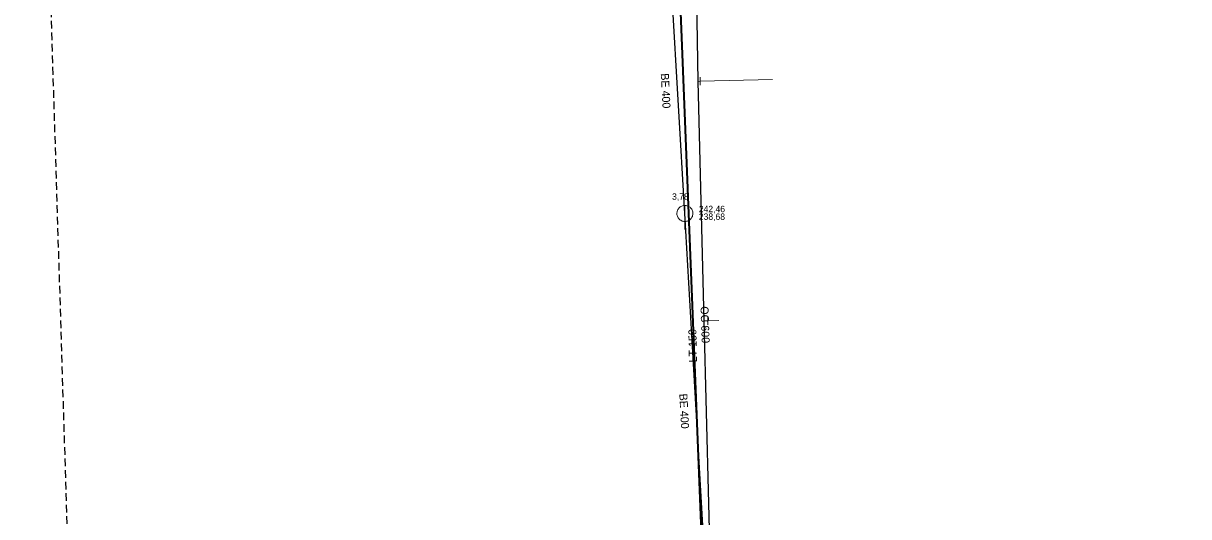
# Model space of a CAD drawing. Extents: x -777996 to -777727, y -976581 to -976199.
# Drawn here: x -777995.4 to -777849.8, y -976378.6 to -976316.9 of the extents above; entities that cross this region are included whole.
import ezdxf

# ---------------------------------------------------------------- set-up
doc = ezdxf.new("R2010")
doc.units = 0
doc.header["$LTSCALE"] = 0.32
doc.linetypes.add('MEDIUM_DASHED', pattern=[4.5, 3, -1.5])
for name, color, linetype, lineweight in [('1', 7, 'MEDIUM_DASHED', 25), ('13', 7, 'Continuous', 13), ('14', 7, 'Continuous', 25), ('17', 7, 'Continuous', 25), ('22', 7, 'Continuous', 13), ('34', 7, 'Continuous', 13)]:
    doc.layers.add(name, color=color, linetype=linetype, lineweight=lineweight)

msp = doc.modelspace()

# ---------------------------------------------------------------- linework, layer by layer
at = {"layer": '1'}
msp.add_lwpolyline([(-777995.417, -976203.033), (-777848.18, -976198.846), (-777864.927, -976230.247), (-777726.762, -976491.225), (-777789.565, -976581.242), (-777941.686, -976558.215), (-777989.136, -976405.396)], close=True, dxfattribs=at)
at = {"layer": '13'}
for p, q in [((-777910.871, -976324.184), (-777901.835, -976323.954)), ((-777909.92, -976354.12), (-777908.556, -976354.054))]:
    msp.add_line(p, q, dxfattribs=at)
at = {"layer": '14'}
for p, q in [((-777912.781, -976340.699), (-777914.489, -976311.478)), ((-777909.866, -976391.528), (-777912.781, -976340.699))]:
    msp.add_line(p, q, dxfattribs=at)
at = {"layer": '14', "lineweight": 13}
for p, q in [((-777911.171, -976324.191), (-777910.871, -976324.184)), ((-777910.419, -976354.124), (-777909.92, -976354.12))]:
    msp.add_line(p, q, dxfattribs=at)
at = {"layer": '17', "lineweight": 35}
msp.add_lwpolyline([(-777904.212, -976563.887), (-777912, -976559.699), (-777928.6, -976551.899), (-777943.399, -976543.899), (-777945.899, -976539.199), (-777934, -976487.1), (-777919.8, -976463.1), (-777903.899, -976437), (-777908, -976421.399), (-777910, -976398.3), (-777913.399, -976312.399), (-777914.899, -976265.1)], dxfattribs=at)
at = {"layer": '17'}
msp.add_lwpolyline([(-777913.344, -976268.857), (-777912.789, -976277.989), (-777911.427, -976308.781), (-777911.171, -976324.191), (-777910.419, -976354.125), (-777909.559, -976388.363), (-777908.825, -976391.646), (-777908.211, -976394.397)], dxfattribs=at)
at = {"layer": '22'}
msp.add_line((-777912.781, -976342.699), (-777912.78, -976339.699), dxfattribs=at)
msp.add_lwpolyline([(-777911.781, -976340.699), (-777911.786, -976340.59), (-777911.804, -976340.482), (-777911.834, -976340.376), (-777911.874, -976340.275), (-777911.926, -976340.178), (-777911.988, -976340.088), (-777912.06, -976340.005), (-777912.14, -976339.931), (-777912.228, -976339.865), (-777912.322, -976339.81), (-777912.422, -976339.765), (-777912.527, -976339.732), (-777912.634, -976339.71), (-777912.743, -976339.7), (-777912.853, -976339.702), (-777912.961, -976339.716), (-777913.068, -976339.741), (-777913.171, -976339.778), (-777913.269, -976339.827), (-777913.361, -976339.885), (-777913.447, -976339.954), (-777913.524, -976340.031), (-777913.593, -976340.117), (-777913.652, -976340.209), (-777913.7, -976340.307), (-777913.737, -976340.41), (-777913.763, -976340.517), (-777913.777, -976340.625), (-777913.78, -976340.735), (-777913.77, -976340.844), (-777913.749, -976340.951), (-777913.715, -976341.055), (-777913.671, -976341.155), (-777913.616, -976341.25), (-777913.55, -976341.338), (-777913.476, -976341.418), (-777913.393, -976341.49), (-777913.303, -976341.552), (-777913.207, -976341.604), (-777913.105, -976341.645), (-777913, -976341.675), (-777912.892, -976341.693), (-777912.782, -976341.699), (-777912.673, -976341.693), (-777912.565, -976341.675), (-777912.46, -976341.646), (-777912.358, -976341.605), (-777912.261, -976341.553), (-777912.171, -976341.491), (-777912.088, -976341.42), (-777912.013, -976341.34), (-777911.948, -976341.252), (-777911.892, -976341.158), (-777911.848, -976341.058), (-777911.814, -976340.954), (-777911.792, -976340.846), (-777911.782, -976340.737)], close=True, dxfattribs=at)
at = {"layer": '34'}
for p, q in [((-777910.883, -976323.684), (-777910.859, -976324.683)), ((-777909.925, -976353.62), (-777909.915, -976354.619))]:
    msp.add_line(p, q, dxfattribs=at)

# ---------------------------------------------------------------- texts
at = {"layer": '1'}
for s, rotation, p in [('BE 400', 273, (-777915.792, -976323.209)), ('OC 600', 272, (-777910.833, -976352.313)), ('LT 150', 91, (-777911.274, -976359.3)), ('BE 400', 273, (-777913.476, -976363.231))]:
    msp.add_text(s, height=1, rotation=rotation, dxfattribs=at).set_placement(p)
msp.add_text('3,78', height=0.8, dxfattribs=at).set_placement((-777914.38, -976338.987))
at = {"layer": '22'}
for s, p in [('242,46', (-777911.038, -976340.538)), ('238,68', (-777911.038, -976341.498))]:
    msp.add_text(s, height=0.8, dxfattribs=at).set_placement(p)

doc.saveas('drawing.dxf')
